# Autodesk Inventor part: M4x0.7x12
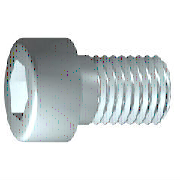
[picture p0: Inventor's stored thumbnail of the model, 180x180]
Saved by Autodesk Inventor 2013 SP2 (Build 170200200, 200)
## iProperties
IsCustomPart: 0
Created: 2016-05
Part Number: M4x0.7x12
Material: 강, 연강
Description: 6각머리 태핑 나사
Document SubType Name: Modeling
Standard: KS B 1003
Designer: mduedu
Standards Organization: KS
Language: ko-KR
Size Designation: M 4 x 12
Categories: <MemberInstance><Categories><Category DisplayName="조임쇠" InternalName="e4da775c-781d-43d5-af7c-5136215cf5a6" Mnemonic="FSTN"><Category DisplayName="볼트" InternalN
Density: 1 g/cm^3
Author: mduedu
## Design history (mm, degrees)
sketch "스케치1"
  geometry: L1 (-1, 0)-(12, 0); L2 (12, 0)-(12, 2); L3 (12, 2)-(1.75, 2); L4 (1.75, 2)-(1.32, 2); L5 (1.32, 2)-(0, 2); L6 (0, 2)-(0, 3.5); L7 (0, 3.5)-(-4, 3.5); L8 (-4, 3.5)-(-4, 1.732); L9 (-4, 1.732)-(-2, 1.732); L10 (-2, 1.732)-(-1, 0); L11 (-7.2, 0)-(15.2, 0) reference; L12 (0, -0.7)-(0, 4.2) reference; L13 (1.75, 2)-(0, 2)
  constraints: 22 end point, 6 parallel, 2 collinear, 2 perpendicular, 1 horizontal, 1 point on line
  dimensions: "d1" = 10.25 distance from line of L3.end L2 (= GEL); "d2" = 0.42952 distance of L4.end L3.end (computed from GAL); "d3" = 4 distance between parallel lines of L8 L6 (= KOH); "d4" = 2 distance of L8.end L9.end (= INTI); "d5" = 60 deg angle of L10 L1; "d6" = 4 diameter of L3 L1 (= GD); "d7" = 4 diameter of L5 L1 (= BDM); "d8" = 3.4641 diameter of L9 L1 (= 1.1547 x SW); "d9" = 7 diameter of L7 L1 (= KOD); "d26" = 12 distance between parallel lines of L12 L2 (= NLG)
revolve "본체" sketch "스케치1" stored, may be unused: angle "d10" = 90 deg
sketch "스케치2"
  geometry: L1 (0, -4.9)-(0, 4.9) reference; L2 (-4.9, 0)-(4.9, 0) reference; L3 (1.732, 0)-(0.866, -1.5); L4 (0.866, -1.5)-(-0.866, -1.5); L5 (-0.866, -1.5)-(-1.732, 0); L6 (-1.732, 0)-(-0.866, 1.5); L7 (-0.866, 1.5)-(0.866, 1.5); L8 (0.866, 1.5)-(1.732, 0); 2 further points
  constraints: 12 end point, 1 coincident, 1 horizontal alignment, 1 point on line, 12 other
extrude "슬롯" join sketch "스케치2" stored distance "d11" = 10; taper "d12" = 0 deg
workplane "Work Plane1"
fillet "Fillet2" dims "d30" = 0.1 (= R)
body "Solid1"
fillet "모깎기1" dims "d17" = 0.4 (= RR)
feature "스레드" dims "d13" = 10.25 (= GEL), "d14" = 0
chamfer "모따기1" distance "d15" = 0.42941 (= -0.5 x SPD + 0.5 x GD); stored, may be unused: second distance "d16" = 0.42941 (= GUL), angle "d27" = 45 deg
other parameters: "GD" = 4 (= NND) [user parameter; used in 2 equation terms], "NLG" = 12 [user parameter; used in 1 equation term], "GEL" = 10.25 [user parameter; used in 2 equation terms], "KOD" = 7 [user parameter; used in 1 equation term], "KOH" = 4 [user parameter; used in 1 equation term], "INTI" = 2 [user parameter; used in 1 equation term], "GAL" = 0.42941 (= 0.61345 x PTC) [user parameter; used in 1 equation term], "GUL" = 0.42941 (= 0.61345 x PTC) [user parameter; used in 1 equation term], "BDM" = 4 (= NND) [user parameter; used in 1 equation term], "SW" = 3 [user parameter; used in 2 equation terms], "RR" = 0.4 [user parameter; used in 1 equation term], "SPD" = 3.14117 (= NND - 1.2269 x PTC) [user parameter; used in 1 equation term], "d19" = 0, "d28" = 0, "d29" = 0, "R" = 0.1 [user parameter; used in 1 equation term], "PHH" = 0.2 [user parameter], "GD1" = 3.14117 (= THREADDIA - 1.2269 x PTC) [user parameter], "THREADDIA" = 4 [user parameter; used in 1 equation term], "FAWI" = 45 deg [user parameter], "TPU" = 14.28571 (computed from PTC) [user parameter], "PTC" = 0.7 [user parameter; used in 5 equation terms], "NND" = 4 [user parameter; used in 3 equation terms], "TOA" = 30 deg [user parameter], "E0" = 3.465 (= 1.155 x SW) [user parameter]
